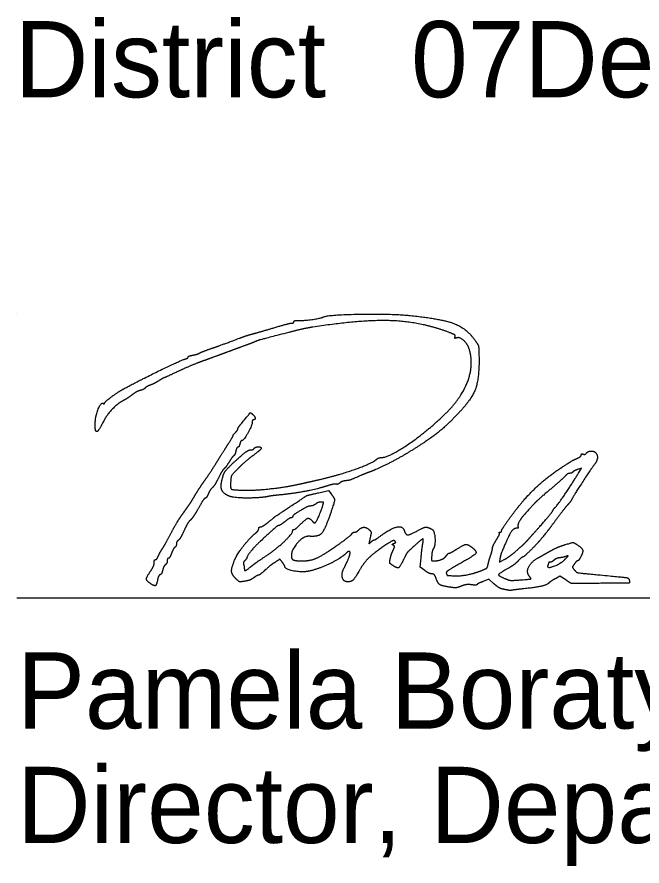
# Model space of a CAD drawing. Extents: x 0 to 34, y 0 to 22.
# Drawn here: x 24.532 to 25.68, y 7.064 to 8.624 of the extents above; entities that cross this region are included whole.
import ezdxf

# ---------------------------------------------------------------- set-up
doc = ezdxf.new("R2010")
doc.units = 0
for name, color, linetype in [('Default', 7, 'Continuous'), ('SH_Data', 7, 'Continuous'), ('SH_Text', 7, 'Continuous')]:
    doc.layers.add(name, color=color, linetype=linetype)

msp = doc.modelspace()

# ---------------------------------------------------------------- linework, layer by layer
at = {"layer": 'Default'}
for points in [[(25.5638, 7.7861), (25.5692, 7.795), (25.5618, 7.7925)], [(25.0865, 7.75), (25.1045, 7.754), (25.1092, 7.7478)], [(25.2814, 7.6071), (25.2731, 7.6135), (25.2745, 7.6305)], [(25.4194, 7.6291), (25.4184, 7.6227), (25.427, 7.6271)], [(25.5402, 7.5898), (25.5296, 7.5966), (25.5212, 7.5921)], [(25.4084, 7.5828), (25.3992, 7.5911), (25.3886, 7.587)]]:
    msp.add_lwpolyline(points, dxfattribs=at)
for points in [[(25.0939, 8.0725), (25.1007, 8.0767), (25.2177, 8.079), (25.2521, 8.0756)], [(25.0041, 8.0529), (25.0202, 8.0577), (25.0351, 8.0616), (25.0371, 8.0616)], [(25.0371, 8.0616), (25.0392, 8.0616), (25.0409, 8.0627), (25.0409, 8.0641)], [(25.0409, 8.0641), (25.0409, 8.0655), (25.0449, 8.0665), (25.0499, 8.0663)], [(25.0499, 8.0663), (25.0595, 8.066), (25.0905, 8.0704), (25.0939, 8.0725)], [(25.3246, 8.0449), (25.274, 8.0639), (25.166, 8.0679), (25.0757, 8.0541)], [(25.2521, 8.0756), (25.3113, 8.0698), (25.3589, 8.0515), (25.3747, 8.0284)], [(24.9653, 8.0418), (24.9706, 8.0432), (24.988, 8.0482), (25.0041, 8.0529)], [(25.0757, 8.0541), (25.0664, 8.0527), (25.0465, 8.0483), (25.0313, 8.0444)], [(24.8849, 8.0134), (24.8996, 8.0185), (24.906, 8.0208), (24.9413, 8.0339)], [(24.9413, 8.0339), (24.9492, 8.0369), (24.96, 8.0404), (24.9653, 8.0418)], [(25.0313, 8.0444), (24.9803, 8.0312), (24.976, 8.03), (24.9653, 8.0256)], [(25.3369, 8.0362), (25.3379, 8.0388), (25.3344, 8.0412), (25.3246, 8.0449)], [(25.3393, 8.0342), (25.3367, 8.0332), (25.336, 8.0338), (25.3369, 8.0362)], [(25.3627, 8.0143), (25.3594, 8.024), (25.345, 8.0364), (25.3393, 8.0342)], [(24.9425, 8.0171), (24.9326, 8.0135), (24.9175, 8.0079), (24.9089, 8.0047)], [(24.9653, 8.0256), (24.9626, 8.0245), (24.9524, 8.0207), (24.9425, 8.0171)], [(25.3747, 8.0284), (25.3796, 8.0212), (25.3805, 8.0169), (25.3809, 7.999)], [(24.8411, 7.9955), (24.8441, 7.9964), (24.8465, 7.998), (24.8465, 7.9991)], [(24.8465, 7.9991), (24.8465, 8.0002), (24.8505, 8.0018), (24.8555, 8.0027)], [(24.8555, 8.0027), (24.8604, 8.0037), (24.8656, 8.0052), (24.8669, 8.0062)], [(24.8669, 8.0062), (24.8682, 8.0072), (24.8763, 8.0104), (24.8849, 8.0134)], [(24.9089, 8.0047), (24.9003, 8.0015), (24.8841, 7.9956), (24.8729, 7.9916)], [(25.3172, 7.8931), (25.3481, 7.9225), (25.372, 7.986), (25.3627, 8.0143)], [(24.7289, 7.9412), (24.7591, 7.9574), (24.8327, 7.9931), (24.8411, 7.9955)], [(24.8729, 7.9916), (24.8617, 7.9876), (24.8413, 7.979), (24.8277, 7.9726)], [(25.3809, 7.999), (25.3816, 7.9582), (25.3655, 7.9185), (25.3361, 7.8886)], [(24.8277, 7.9726), (24.814, 7.9661), (24.8024, 7.9608), (24.8018, 7.9608)], [(24.7918, 7.9551), (24.7869, 7.952), (24.7802, 7.9487), (24.777, 7.9476)], [(24.8018, 7.9608), (24.8012, 7.9608), (24.7968, 7.9582), (24.7918, 7.9551)], [(24.6929, 7.9146), (24.6929, 7.9167), (24.7183, 7.9355), (24.7289, 7.9412)], [(24.7581, 7.9376), (24.7546, 7.9368), (24.7479, 7.9331), (24.7433, 7.9296)], [(24.7678, 7.9425), (24.766, 7.9407), (24.7617, 7.9385), (24.7581, 7.9376)], [(24.777, 7.9476), (24.7738, 7.9466), (24.7696, 7.9443), (24.7678, 7.9425)], [(24.7433, 7.9296), (24.7387, 7.926), (24.7315, 7.9213), (24.7274, 7.9192)], [(24.6757, 7.8767), (24.6758, 7.8899), (24.6864, 7.9165), (24.6906, 7.9139)], [(24.6906, 7.9139), (24.6918, 7.9131), (24.6929, 7.9134), (24.6929, 7.9146)], [(24.7274, 7.9192), (24.717, 7.9139), (24.6971, 7.893), (24.6909, 7.8809)], [(24.9431, 7.8756), (24.9616, 7.8978), (24.9609, 7.8972), (24.965, 7.8938)], [(24.965, 7.8938), (24.9693, 7.8903), (24.9702, 7.884), (24.9665, 7.884)], [(25.2005, 7.8144), (25.2146, 7.8144), (25.2827, 7.8603), (25.3172, 7.8931)], [(24.6771, 7.863), (24.6763, 7.8638), (24.6757, 7.87), (24.6757, 7.8767)], [(24.6909, 7.8809), (24.6842, 7.868), (24.6789, 7.8611), (24.6771, 7.863)], [(24.9377, 7.867), (24.9377, 7.8682), (24.9401, 7.8721), (24.9431, 7.8756)], [(24.9641, 7.8789), (24.9641, 7.8734), (24.9482, 7.8456), (24.945, 7.8456)], [(24.9665, 7.884), (24.9652, 7.884), (24.9641, 7.8817), (24.9641, 7.8789)], [(25.3361, 7.8886), (25.3175, 7.8697), (25.2851, 7.8448), (25.2546, 7.826)], [(24.9291, 7.8552), (24.9286, 7.8552), (24.9302, 7.8574), (24.9329, 7.86)], [(24.9329, 7.86), (24.9355, 7.8626), (24.9377, 7.8658), (24.9377, 7.867)], [(24.9201, 7.8395), (24.9257, 7.8481), (24.9297, 7.8552), (24.9291, 7.8552)], [(24.945, 7.8456), (24.9439, 7.8456), (24.9423, 7.8429), (24.9415, 7.8396)], [(24.8981, 7.8045), (24.9047, 7.8152), (24.9146, 7.8309), (24.9201, 7.8395)], [(24.9293, 7.8046), (24.945, 7.8193), (24.9577, 7.8288), (24.9617, 7.8288)], [(24.9378, 7.8336), (24.9366, 7.8336), (24.935, 7.8304), (24.9341, 7.8264)], [(24.9415, 7.8396), (24.9407, 7.8363), (24.939, 7.8336), (24.9378, 7.8336)], [(24.9617, 7.8288), (24.9642, 7.8288), (24.9669, 7.8299), (24.9677, 7.8312)], [(24.9809, 7.8316), (24.9809, 7.8304), (24.9741, 7.8245), (24.9659, 7.8184)], [(24.9677, 7.8312), (24.9695, 7.8341), (24.9809, 7.8344), (24.9809, 7.8316)], [(24.9302, 7.8178), (24.9289, 7.817), (24.9251, 7.8119), (24.9217, 7.8064)], [(24.9341, 7.8264), (24.9332, 7.8225), (24.9315, 7.8186), (24.9302, 7.8178)], [(24.9659, 7.8184), (24.9576, 7.8123), (24.9451, 7.8015), (24.9381, 7.7943)], [(25.2546, 7.826), (25.2354, 7.8141), (25.1942, 7.7932), (25.1801, 7.7881)], [(25.1923, 7.8111), (25.1944, 7.8129), (25.198, 7.8144), (25.2005, 7.8144)], [(25.5321, 7.796), (25.551, 7.8083), (25.5529, 7.8093), (25.5611, 7.813)], [(25.5611, 7.813), (25.5654, 7.815), (25.5689, 7.8178), (25.5689, 7.8193)], [(25.5689, 7.8193), (25.5689, 7.8209), (25.5704, 7.8215), (25.5723, 7.8208)], [(25.5723, 7.8208), (25.5742, 7.8201), (25.577, 7.821), (25.5786, 7.8229)], [(25.5786, 7.8229), (25.5802, 7.8248), (25.5839, 7.8264), (25.5868, 7.8264)], [(25.5868, 7.8264), (25.5962, 7.8264), (25.6, 7.8103), (25.5926, 7.8014)], [(24.8763, 7.7716), (24.8817, 7.7791), (24.8915, 7.7939), (24.8981, 7.8045)], [(24.9079, 7.77), (24.9107, 7.783), (24.9168, 7.793), (24.9293, 7.8046)], [(24.9217, 7.8064), (24.9183, 7.8009), (24.9142, 7.7953), (24.9125, 7.794)], [(25.0805, 7.7725), (25.1174, 7.7807), (25.1837, 7.8035), (25.1923, 7.8111)], [(25.5926, 7.8014), (25.5884, 7.7963), (25.5556, 7.7459), (25.5524, 7.7397)], [(24.9125, 7.794), (24.9109, 7.7926), (24.9062, 7.785), (24.9022, 7.777)], [(24.9381, 7.7943), (24.9274, 7.7834), (24.9252, 7.7797), (24.9247, 7.7715)], [(25.1644, 7.7819), (25.1474, 7.7744), (25.1425, 7.7727), (25.1359, 7.772)], [(25.1801, 7.7881), (25.1755, 7.7864), (25.1684, 7.7836), (25.1644, 7.7819)], [(25.4375, 7.7035), (25.4597, 7.7343), (25.5048, 7.7783), (25.5321, 7.796)], [(25.521, 7.7232), (25.5238, 7.7251), (25.552, 7.7666), (25.5638, 7.7861)], [(25.5478, 7.7856), (25.5456, 7.7856), (25.5416, 7.7832), (25.539, 7.7802)], [(25.5531, 7.7878), (25.5524, 7.7866), (25.55, 7.7856), (25.5478, 7.7856)], [(25.5618, 7.7925), (25.5578, 7.7911), (25.5539, 7.7889), (25.5531, 7.7878)], [(24.8596, 7.746), (24.8634, 7.7526), (24.871, 7.7641), (24.8763, 7.7716)], [(24.9022, 7.777), (24.8982, 7.769), (24.8931, 7.761), (24.8909, 7.7592)], [(24.9233, 7.7432), (24.9128, 7.7471), (24.9057, 7.7595), (24.9079, 7.77)], [(24.9247, 7.7715), (24.9238, 7.758), (24.9279, 7.7551), (24.9485, 7.7546)], [(25.0469, 7.765), (25.0548, 7.7667), (25.0699, 7.7701), (25.0805, 7.7725)], [(25.1183, 7.7657), (25.1166, 7.7663), (25.1085, 7.7646), (25.1003, 7.762)], [(25.1251, 7.7679), (25.123, 7.7661), (25.1199, 7.7651), (25.1183, 7.7657)], [(25.1359, 7.772), (25.132, 7.7715), (25.1271, 7.7697), (25.1251, 7.7679)], [(25.539, 7.7802), (25.5363, 7.7772), (25.5238, 7.7662), (25.5113, 7.7556)], [(24.8909, 7.7592), (24.8888, 7.7574), (24.8855, 7.7524), (24.8837, 7.748)], [(24.9485, 7.7546), (24.9677, 7.7541), (25.0256, 7.7602), (25.0469, 7.765)], [(25.1003, 7.762), (25.0838, 7.7567), (25.0387, 7.7482), (25.0149, 7.7459)], [(25.0325, 7.7235), (25.0641, 7.7446), (25.0655, 7.7452), (25.0865, 7.75)], [(25.5113, 7.7556), (25.4917, 7.7391), (25.48, 7.7277), (25.4633, 7.7088)], [(24.8466, 7.7253), (24.8499, 7.7301), (24.8558, 7.7394), (24.8596, 7.746)], [(24.878, 7.74), (24.8767, 7.74), (24.8713, 7.7321), (24.8659, 7.7224)], [(24.8837, 7.748), (24.8818, 7.7436), (24.8793, 7.74), (24.878, 7.74)], [(24.9945, 7.7433), (24.9808, 7.7402), (24.9313, 7.7402), (24.9233, 7.7432)], [(25.0149, 7.7459), (25.0066, 7.7451), (24.9974, 7.7439), (24.9945, 7.7433)], [(25.1092, 7.7478), (25.1158, 7.7391), (25.1156, 7.7342), (25.1079, 7.7116)], [(25.5524, 7.7397), (25.5507, 7.7363), (25.5468, 7.7308), (25.5438, 7.7276)], [(24.833, 7.7061), (24.8371, 7.712), (24.8432, 7.7206), (24.8466, 7.7253)], [(24.8659, 7.7224), (24.8606, 7.7128), (24.8539, 7.7028), (24.8511, 7.7002)], [(24.9933, 7.6956), (25.007, 7.7067), (25.005, 7.7053), (25.0325, 7.7235)], [(25.0622, 7.7225), (25.0477, 7.7145), (25.0385, 7.7081), (25.0385, 7.7062)], [(25.0719, 7.7256), (25.0697, 7.7256), (25.0653, 7.7242), (25.0622, 7.7225)], [(25.0806, 7.7291), (25.0781, 7.7272), (25.0741, 7.7256), (25.0719, 7.7256)], [(25.0791, 7.6944), (25.0809, 7.6944), (25.0907, 7.7155), (25.0938, 7.7262)], [(25.0905, 7.7327), (25.0876, 7.7327), (25.0832, 7.7311), (25.0806, 7.7291)], [(25.0938, 7.7262), (25.0955, 7.732), (25.0951, 7.7328), (25.0905, 7.7327)], [(25.5171, 7.718), (25.5183, 7.7202), (25.52, 7.7225), (25.521, 7.7232)], [(25.5438, 7.7276), (25.5408, 7.7244), (25.5319, 7.713), (25.524, 7.7024)], [(24.8141, 7.674), (24.8204, 7.6859), (24.8289, 7.7003), (24.833, 7.7061)], [(25.0358, 7.704), (25.0344, 7.704), (25.0291, 7.7008), (25.0241, 7.6968)], [(25.0385, 7.7062), (25.0385, 7.705), (25.0373, 7.704), (25.0358, 7.704)], [(25.0529, 7.692), (25.063, 7.7021), (25.0695, 7.7039), (25.0745, 7.698)], [(25.1079, 7.7116), (25.0976, 7.6817), (25.0856, 7.6687), (25.0697, 7.67)], [(25.4225, 7.6802), (25.4225, 7.6816), (25.4292, 7.6921), (25.4375, 7.7035)], [(25.4633, 7.7088), (25.4574, 7.7022), (25.4512, 7.6893), (25.4526, 7.687)], [(25.4858, 7.6802), (25.5011, 7.6974), (25.5147, 7.7137), (25.5171, 7.718)], [(24.8511, 7.7002), (24.8482, 7.6977), (24.8427, 7.6886), (24.8388, 7.68)], [(24.9761, 7.6838), (24.9761, 7.6856), (24.9776, 7.6872), (24.9795, 7.6872)], [(25.0129, 7.6896), (25.011, 7.6896), (25.0026, 7.6823), (24.9773, 7.6591)], [(24.9795, 7.6872), (24.9813, 7.6872), (24.9875, 7.691), (24.9933, 7.6956)], [(25.0241, 7.6968), (25.0191, 7.6928), (25.0141, 7.6896), (25.0129, 7.6896)], [(25.0409, 7.6824), (25.0422, 7.6824), (25.0476, 7.6867), (25.0529, 7.692)], [(25.0745, 7.698), (25.0761, 7.696), (25.0782, 7.6944), (25.0791, 7.6944)], [(25.1976, 7.6689), (25.2179, 7.6841), (25.2406, 7.6897), (25.2436, 7.6803)], [(25.524, 7.7024), (25.5161, 7.6917), (25.5084, 7.6815), (25.507, 7.6797)], [(24.7987, 7.6464), (24.8009, 7.6497), (24.8078, 7.6621), (24.8141, 7.674)], [(24.8388, 7.68), (24.8348, 7.6714), (24.8301, 7.6635), (24.8283, 7.6625)], [(24.9326, 7.6277), (24.9371, 7.6382), (24.9603, 7.6676), (24.9707, 7.676)], [(24.9707, 7.676), (24.9736, 7.6784), (24.9761, 7.6819), (24.9761, 7.6838)], [(24.9924, 7.6358), (25.008, 7.6462), (25.0385, 7.675), (25.0385, 7.6793)], [(25.0385, 7.6793), (25.0385, 7.681), (25.0396, 7.6824), (25.0409, 7.6824)], [(25.1045, 7.6427), (25.1231, 7.6551), (25.1455, 7.6718), (25.1472, 7.6745)], [(25.1472, 7.6745), (25.1483, 7.6762), (25.1506, 7.6776), (25.1524, 7.6776)], [(25.1524, 7.6776), (25.1542, 7.6776), (25.1575, 7.6793), (25.1596, 7.6815)], [(25.1596, 7.6815), (25.1646, 7.6865), (25.1746, 7.6865), (25.1795, 7.6816)], [(25.1795, 7.6816), (25.1827, 7.6784), (25.1829, 7.6759), (25.1808, 7.6668)], [(25.2436, 7.6803), (25.246, 7.6727), (25.2541, 7.6725), (25.2674, 7.6799)], [(25.2674, 7.6799), (25.2793, 7.6865), (25.2866, 7.6872), (25.2948, 7.6826)], [(25.2948, 7.6826), (25.2992, 7.6802), (25.3008, 7.6522), (25.2969, 7.647)], [(25.4127, 7.6633), (25.4166, 7.6696), (25.4191, 7.6754), (25.4183, 7.6762)], [(25.4183, 7.6762), (25.4175, 7.6769), (25.4181, 7.6776), (25.4197, 7.6776)], [(25.4197, 7.6776), (25.4212, 7.6776), (25.4225, 7.6787), (25.4225, 7.6802)], [(25.4503, 7.6848), (25.444, 7.6848), (25.4345, 7.6696), (25.4224, 7.6404)], [(25.4526, 7.687), (25.4534, 7.6858), (25.4523, 7.6848), (25.4503, 7.6848)], [(25.4702, 7.6628), (25.4733, 7.6663), (25.4803, 7.6742), (25.4858, 7.6802)], [(25.507, 7.6797), (25.4937, 7.6633), (25.4891, 7.6581), (25.4773, 7.6459)], [(24.8249, 7.656), (24.8249, 7.6535), (24.8238, 7.6508), (24.8224, 7.6499)], [(24.8283, 7.6625), (24.8264, 7.6614), (24.8249, 7.6585), (24.8249, 7.656)], [(24.9773, 7.6591), (24.9682, 7.6507), (24.9545, 7.6336), (24.9545, 7.6306)], [(25.0697, 7.67), (25.0593, 7.6709), (25.0361, 7.6455), (25.0361, 7.6333)], [(25.1808, 7.6668), (25.1785, 7.6565), (25.1786, 7.6561), (25.1824, 7.6595)], [(25.1824, 7.6595), (25.1846, 7.6615), (25.1873, 7.6632), (25.1882, 7.6632)], [(25.1882, 7.6632), (25.1892, 7.6632), (25.1934, 7.6658), (25.1976, 7.6689)], [(25.2263, 7.6611), (25.2245, 7.6629), (25.2186, 7.6602), (25.2061, 7.6517)], [(25.2235, 7.6535), (25.2213, 7.6548), (25.2216, 7.6557), (25.2247, 7.6569)], [(25.2247, 7.6569), (25.2277, 7.6581), (25.2281, 7.6593), (25.2263, 7.6611)], [(25.2674, 7.6571), (25.2515, 7.643), (25.2478, 7.6386), (25.2423, 7.6273)], [(25.2775, 7.6554), (25.2793, 7.6648), (25.2767, 7.6653), (25.2674, 7.6571)], [(25.4057, 7.6485), (25.4057, 7.6504), (25.4088, 7.657), (25.4127, 7.6633)], [(25.4501, 7.6439), (25.458, 7.6507), (25.467, 7.6592), (25.4702, 7.6628)], [(25.5394, 7.6546), (25.5534, 7.6588), (25.5546, 7.6589), (25.5605, 7.655)], [(24.7918, 7.6338), (24.7934, 7.6374), (24.7965, 7.6431), (24.7987, 7.6464)], [(24.8224, 7.6499), (24.821, 7.6491), (24.8182, 7.6442), (24.8161, 7.639)], [(25.056, 7.6248), (25.0691, 7.6248), (25.0882, 7.6319), (25.1045, 7.6427)], [(25.1441, 7.6395), (25.1441, 7.6425), (25.1401, 7.6421), (25.1365, 7.6386)], [(25.2061, 7.6517), (25.1864, 7.6382), (25.1692, 7.6212), (25.1609, 7.6068)], [(25.2177, 7.628), (25.2185, 7.6322), (25.2207, 7.6392), (25.2228, 7.6436)], [(25.2228, 7.6436), (25.2256, 7.6499), (25.2258, 7.652), (25.2235, 7.6535)], [(25.2745, 7.6305), (25.2753, 7.6399), (25.2767, 7.6511), (25.2775, 7.6554)], [(25.2969, 7.647), (25.2957, 7.6453), (25.2944, 7.6397), (25.294, 7.6344)], [(25.3265, 7.6392), (25.3277, 7.6392), (25.3338, 7.6424), (25.3401, 7.6464)], [(25.3683, 7.6494), (25.378, 7.6418), (25.3711, 7.6338), (25.3395, 7.6161)], [(25.3401, 7.6464), (25.353, 7.6546), (25.3606, 7.6554), (25.3683, 7.6494)], [(25.4022, 7.6344), (25.4041, 7.6403), (25.4057, 7.6467), (25.4057, 7.6485)], [(25.427, 7.6271), (25.4318, 7.6295), (25.4422, 7.6371), (25.4501, 7.6439)], [(25.4773, 7.6459), (25.4698, 7.6383), (25.4627, 7.632), (25.4617, 7.632)], [(25.4905, 7.6309), (25.4934, 7.6325), (25.5022, 7.6374), (25.5101, 7.6419)], [(25.5101, 7.6419), (25.518, 7.6465), (25.5312, 7.6522), (25.5394, 7.6546)], [(25.5605, 7.655), (25.5701, 7.6487), (25.5725, 7.6413), (25.5679, 7.6323)], [(24.7841, 7.6215), (24.7841, 7.6246), (24.7852, 7.6272), (24.7865, 7.6272)], [(24.7865, 7.6272), (24.7879, 7.6272), (24.7903, 7.6302), (24.7918, 7.6338)], [(24.8081, 7.6251), (24.8081, 7.6226), (24.8065, 7.6193), (24.8046, 7.6177)], [(24.8102, 7.6296), (24.809, 7.6296), (24.8081, 7.6276), (24.8081, 7.6251)], [(24.8161, 7.639), (24.8141, 7.6338), (24.8114, 7.6296), (24.8102, 7.6296)], [(24.9343, 7.592), (24.9266, 7.5996), (24.926, 7.6124), (24.9326, 7.6277)], [(24.9507, 7.6255), (24.9487, 7.6235), (24.9476, 7.6202), (24.9483, 7.6183)], [(24.9545, 7.6306), (24.9545, 7.6299), (24.9528, 7.6276), (24.9507, 7.6255)], [(24.9609, 7.6135), (24.9684, 7.6196), (24.9737, 7.6233), (24.9924, 7.6358)], [(25.0195, 7.6222), (25.015, 7.628), (25.0149, 7.628), (25.0082, 7.6236)], [(25.0361, 7.6333), (25.0361, 7.6281), (25.0439, 7.6248), (25.056, 7.6248)], [(25.1365, 7.6386), (25.1269, 7.6294), (25.0881, 7.6106), (25.0697, 7.6062)], [(25.1335, 7.6128), (25.1376, 7.6205), (25.1441, 7.6367), (25.1441, 7.6395)], [(25.2223, 7.6165), (25.2173, 7.6197), (25.2165, 7.6217), (25.2177, 7.628)], [(25.2423, 7.6273), (25.2356, 7.6135), (25.2308, 7.6109), (25.2223, 7.6165)], [(25.294, 7.6344), (25.2935, 7.6268), (25.2942, 7.6248), (25.2973, 7.6248)], [(25.2973, 7.6248), (25.3057, 7.6248), (25.3177, 7.6296), (25.3209, 7.6343)], [(25.3209, 7.6343), (25.3228, 7.637), (25.3253, 7.6392), (25.3265, 7.6392)], [(25.3974, 7.6173), (25.3981, 7.6208), (25.4002, 7.6285), (25.4022, 7.6344)], [(25.4224, 7.6404), (25.4213, 7.6378), (25.42, 7.6327), (25.4194, 7.6291)], [(25.4531, 7.625), (25.4495, 7.6212), (25.4414, 7.6151), (25.4351, 7.6114)], [(25.4617, 7.632), (25.4606, 7.632), (25.4567, 7.6289), (25.4531, 7.625)], [(25.4735, 7.5965), (25.4674, 7.604), (25.4772, 7.6237), (25.4905, 7.6309)], [(25.5074, 7.6166), (25.5049, 7.6101), (25.5304, 7.6191), (25.5389, 7.6277)], [(25.5185, 7.626), (25.5163, 7.624), (25.5132, 7.6224), (25.5117, 7.6224)], [(25.5295, 7.6305), (25.5256, 7.63), (25.5207, 7.628), (25.5185, 7.626)], [(25.5413, 7.6332), (25.5386, 7.6322), (25.5333, 7.631), (25.5295, 7.6305)], [(25.5389, 7.6277), (25.5444, 7.6333), (25.5449, 7.6346), (25.5413, 7.6332)], [(25.5679, 7.6323), (25.5657, 7.6282), (25.563, 7.6248), (25.5619, 7.6248)], [(24.7783, 7.6073), (24.7815, 7.612), (24.7841, 7.6184), (24.7841, 7.6215)], [(24.8046, 7.6177), (24.8027, 7.6161), (24.8005, 7.6116), (24.7996, 7.6077)], [(24.9483, 7.6183), (24.9491, 7.6164), (24.9497, 7.6133), (24.9497, 7.6114)], [(24.9497, 7.6114), (24.9497, 7.6065), (24.9531, 7.6072), (24.9609, 7.6135)], [(25.0082, 7.6236), (25, 7.6182), (24.9974, 7.6162), (24.9862, 7.6062)], [(25.024, 7.6149), (25.024, 7.6157), (25.022, 7.619), (25.0195, 7.6222)], [(25.0697, 7.6062), (25.0568, 7.6031), (25.0242, 7.6093), (25.024, 7.6149)], [(25.1402, 7.5864), (25.1318, 7.5864), (25.1278, 7.6022), (25.1335, 7.6128)], [(25.3395, 7.6161), (25.3263, 7.6087), (25.3201, 7.6039), (25.3209, 7.6017)], [(25.3847, 7.6067), (25.3935, 7.6101), (25.3964, 7.6125), (25.3974, 7.6173)], [(25.4351, 7.6114), (25.4172, 7.601), (25.4161, 7.5977), (25.4291, 7.5922)], [(25.5089, 7.6214), (25.5089, 7.6208), (25.5082, 7.6187), (25.5074, 7.6166)], [(25.5117, 7.6224), (25.5101, 7.6224), (25.5089, 7.6219), (25.5089, 7.6214)], [(25.556, 7.619), (25.5525, 7.6136), (25.5525, 7.6128), (25.5564, 7.608)], [(25.5619, 7.6248), (25.5608, 7.6248), (25.5581, 7.6222), (25.556, 7.619)], [(24.7766, 7.5836), (24.7696, 7.5884), (24.77, 7.5952), (24.7783, 7.6073)], [(24.7949, 7.5993), (24.7932, 7.5986), (24.7911, 7.5945), (24.7903, 7.5901)], [(24.7996, 7.6077), (24.7987, 7.6037), (24.7966, 7.5999), (24.7949, 7.5993)], [(24.967, 7.5937), (24.9634, 7.5911), (24.956, 7.5882), (24.9505, 7.5874)], [(24.9755, 7.5984), (24.9744, 7.5984), (24.9706, 7.5963), (24.967, 7.5937)], [(24.9862, 7.6062), (24.9814, 7.6019), (24.9766, 7.5984), (24.9755, 7.5984)], [(25.1609, 7.6068), (25.1527, 7.5927), (25.1463, 7.5864), (25.1402, 7.5864)], [(25.2944, 7.6008), (25.2918, 7.6008), (25.286, 7.6036), (25.2814, 7.6071)], [(25.3019, 7.593), (25.3001, 7.5982), (25.2975, 7.6008), (25.2944, 7.6008)], [(25.3209, 7.6017), (25.3222, 7.5983), (25.3229, 7.598), (25.3349, 7.5974)], [(25.3349, 7.5974), (25.3454, 7.5967), (25.3715, 7.6016), (25.3847, 7.6067)], [(25.4559, 7.5898), (25.4754, 7.5913), (25.4772, 7.592), (25.4735, 7.5965)], [(25.5564, 7.608), (25.56, 7.6035), (25.565, 7.6025), (25.5989, 7.5994)], [(25.5989, 7.5994), (25.648, 7.5948), (25.6562, 7.5933), (25.6572, 7.5885)], [(24.7903, 7.5901), (24.7884, 7.5803), (24.7842, 7.5783), (24.7766, 7.5836)], [(24.9505, 7.5874), (24.9418, 7.586), (24.9396, 7.5867), (24.9343, 7.592)], [(25.3273, 7.5765), (25.3123, 7.5789), (25.3054, 7.5833), (25.3019, 7.593)], [(25.3484, 7.5784), (25.3414, 7.5756), (25.3359, 7.5751), (25.3273, 7.5765)], [(25.3673, 7.5809), (25.3615, 7.5817), (25.3542, 7.5807), (25.3484, 7.5784)], [(25.3774, 7.5813), (25.377, 7.5804), (25.3724, 7.5802), (25.3673, 7.5809)], [(25.3886, 7.587), (25.3828, 7.5848), (25.3778, 7.5822), (25.3774, 7.5813)], [(25.423, 7.5733), (25.42, 7.574), (25.4134, 7.5782), (25.4084, 7.5828)], [(25.4291, 7.5922), (25.4359, 7.5893), (25.4424, 7.5887), (25.4559, 7.5898)], [(25.5095, 7.5843), (25.5058, 7.5805), (25.4843, 7.5757), (25.4609, 7.5733)], [(25.5212, 7.5921), (25.5166, 7.5896), (25.5113, 7.5861), (25.5095, 7.5843)], [(25.5869, 7.5834), (25.5512, 7.583), (25.5508, 7.5831), (25.5402, 7.5898)], [(25.6572, 7.5885), (25.658, 7.5843), (25.656, 7.5841), (25.5869, 7.5834)], [(25.4333, 7.5712), (25.4306, 7.5717), (25.426, 7.5727), (25.423, 7.5733)], [(25.4417, 7.5709), (25.4397, 7.5705), (25.4359, 7.5706), (25.4333, 7.5712)], [(25.4609, 7.5733), (25.4523, 7.5724), (25.4437, 7.5713), (25.4417, 7.5709)]]:
    msp.add_open_spline(points, degree=2, dxfattribs=at)
at = {"layer": 'SH_Data'}
for p, q in [((24.532, 8.0789), (24.532, 8.0789)), ((24.532, 7.5567), (28.032, 7.5567))]:
    msp.add_line(p, q, dxfattribs=at)

# ---------------------------------------------------------------- texts
at = {"layer": 'SH_Text'}
for s, p in [('District       Deputy Director', (24.5279, 8.4762)), ('              07', (24.5279, 8.4762)), ('Pamela Boratyn', (24.532, 7.3167)), ('Director, Department of Transportation', (24.532, 7.1067))]:
    msp.add_text(s, height=0.14, dxfattribs=at).set_placement(p)

doc.saveas('drawing.dxf')
